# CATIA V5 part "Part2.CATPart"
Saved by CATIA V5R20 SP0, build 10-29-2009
Part number: 花瓶
Bounding box of the stored display mesh (mm): x -77.814 to 79.189, y -64.235 to 73.538, z -61 to 128.883
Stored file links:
  C:\Users\16057\Desktop\花瓶\Part2.CATPart
  C:\CATIAR20\win_b64\startup\materials\Catalog.CATMaterial
  C:\CATIAR20\win_b64\startup\materials\blue_env_512x512.jpg
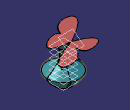
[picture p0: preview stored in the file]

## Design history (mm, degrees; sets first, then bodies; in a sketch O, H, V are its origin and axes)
Body1 (main body), material "无"
  Plane1: type Offset, RefPlane xy-plane, Offset 20
  Plane2: type Offset, RefPlane xy-plane, Offset 20, reversed
  Plane3: type Offset, RefPlane Plane2, Offset 20, reversed
  Plane4: type Offset, RefPlane Plane1, Offset 20
  Plane5: type Offset, RefPlane Plane4, Offset 20
  Plane6: type Offset, RefPlane Plane3, Offset 20
  Plane7: type Offset, RefPlane Plane3, Offset 20, reversed
  Sketch1 on Plane5, origin (0, 0, 60), H (1, 0, 0), V (0, 1, 0)
    circle A1 centre (0, 0) radius 18
  Sketch2 on Plane4, origin (0, 0, 40), H (1, 0, 0), V (0, 1, 0)
    circle A1 centre (0, 0) radius 15
  Sketch3 on Plane1, origin (0, 0, 20), H (1, 0, 0), V (0, 1, 0)
    circle A1 centre (0, 0) radius 20
  Sketch4 on xy-plane, origin (0, 0, 0), H (1, 0, 0), V (0, 1, 0)
    circle A1 centre (0, 0) radius 41.2311
  Sketch5 on Plane6, origin (0, 0, -20), H (1, 0, 0), V (0, 1, 0)
    circle A1 centre (0, 0) radius 63.2456
  Sketch6 on Plane3, origin (0, 0, -40), H (1, 0, 0), V (0, 1, 0)
    circle A1 centre (0, 0) radius 50
  Sketch7 on Plane7, origin (0, 0, -60), H (1, 0, 0), V (0, 1, 0)
    circle A1 centre (0, 0) radius 30
    point P1 (30, 0)
    coincidence: A1 P1, P1 H
  Loft1: solid, Sections (Sketch1; Sketch2; Sketch3; Sketch4; Sketch5; Sketch6; Sketch7)
  Shell1: IntOffset 1, Face face of Loft1, ExtOffset 1
Body2
  Sketch8 on yz-plane, origin (0, 0, 0), H (0, 1, 0), V (0, 0, 1)
    axis line L1 (0, -60) -> (0, 0)
    point P1 (0, -60)
    point P2 (0, -20)
    line L2 (0, -20) -> (60, -20)
    line L3 (60, -20) -> (30, -60)
    line L4 (30, -60) -> (0, -60)
    line L5 (0, -60) -> (0, -20)
    coincidence: P1 V, P2 L1
    vertical: L1 V, L5 V
    horizontal: L2 H, L4 H
  Shaft1: profile Sketch8, axis Sketch8.L5, angle 360
  Sketch9 on yz-plane, origin (0, 0, 0), H (0, 1, 0), V (0, 0, 1)
    spline S1 through (0, -60) (0, 30) (30, 90)
  Plane8: type Normal, Curve Sketch9, RefPoint vertex of Sketch9
  Circle1: type CtrRad, Start 0, End 180, Center vertex of Sketch9, Support Plane8, Radius 2.5, FirstDirection (1, 0, 0)
  Rib1: profile Circle1, centre curve Sketch9
  Sketch10 on Plane8, origin (0, 54.0483, 71.9301), H (1, 0, 0), V (0, -0.7995, 0.6007)
    spline S1 through (0, 30) (-70, -10) (-20, -10) (0, 30)
    point P1 (0, 30)
    point P2 (0, 30)
    coincidence: P1 V, P2 P1
  Pad1: profile Sketch10, direction (0, -0.6007, -0.7995), length 2
  Sketch11 on Plane8, origin (0, 54.0483, 71.9301), H (1, 0, 0), V (0, -0.7995, 0.6007)
    spline S1 through (0, 30) (70, -20) (20, -20) (0, 30)
    point P1 (0, 30)
    point P2 (0, 30)
    coincidence: P1 V, P2 P1
  Pad2: profile Sketch11, direction (0, -0.6007, -0.7995), length 2
  Sketch12 on Plane8, origin (0, 54.0483, 71.9301), H (1, 0, 0), V (0, -0.7995, 0.6007)
    spline S1 through (0, 30) (70, 60) (30, 80) (0, 30)
    point P1 (0, 30)
    point P2 (0, 30)
    coincidence: P1 V, P2 P1
  Pocket1: profile Sketch12, direction (0, 0.6007, 0.7995), length 2
  Sketch13 on Plane8, origin (0, 54.0483, 71.9301), H (1, 0, 0), V (0, -0.7995, 0.6007)
    spline S1 through (0, 30) (70, 60) (30, 70) (0, 30)
    point P1 (0, 30)
    point P2 (0, 30)
    coincidence: P1 V, P2 P1
  Pad3: profile Sketch13, direction (0, -0.6007, -0.7995), length 2
  Sketch14 on Plane8, origin (0, 54.0483, 71.9301), H (1, 0, 0), V (0, -0.7995, 0.6007)
    spline S1 through (0, 30) (0, 90) (-50, 90) (0, 30)
    point P1 (0, 30)
    point P2 (0, 30)
    coincidence: P1 V, P2 P1
  Pad4: profile Sketch14, direction (0, -0.6007, -0.7995), length 2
